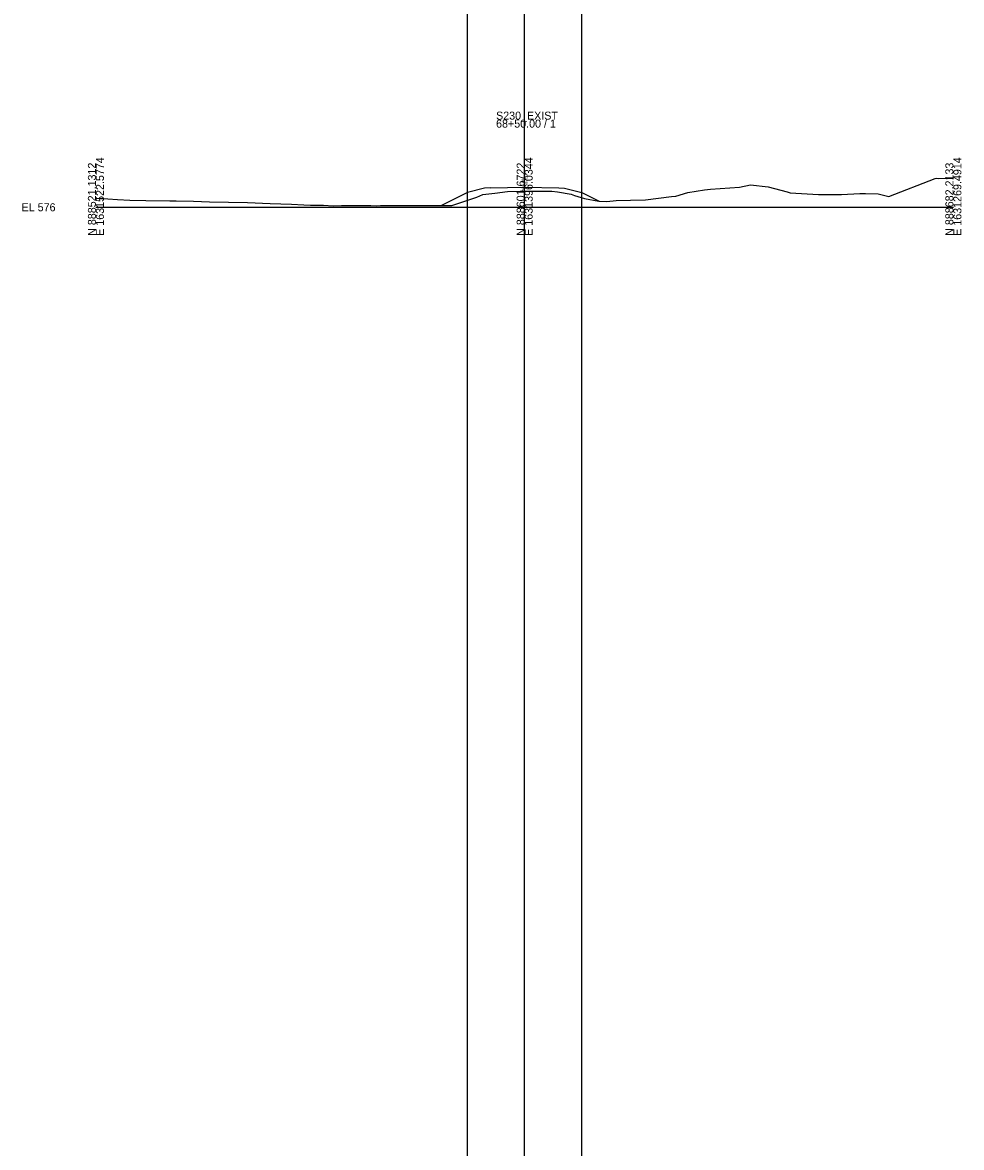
# Model space of a CAD drawing. Extents: x 1631115 to 1631443, y 885974 to 892071.
# Drawn here: x 1631114.8 to 1631443.3, y 887154.7 to 887548.3 of the extents above; entities that cross this region are included whole.
import ezdxf

# ---------------------------------------------------------------- set-up
doc = ezdxf.new("R2010")
doc.units = 0
for name, color, linetype in [('Default', 7, 'Continuous'), ('RD_GPK_XS_Cell', 7, 'Continuous'), ('RD_XS_EarthShd', 7, 'Continuous'), ('RD_XS_ExGround', 7, 'Continuous'), ('RD_XS_Pave', 7, 'Continuous'), ('RD_XS_TieSlope', 7, 'Continuous'), ('RD_XS_TX_Elev_EX', 7, 'Continuous'), ('RD_XS_TX_Elev_PR', 7, 'Continuous')]:
    doc.layers.add(name, color=color, linetype=linetype)

msp = doc.modelspace()

# ---------------------------------------------------------------- linework, layer by layer
at = {"layer": 'Default'}
for p, q in [((1631270.47, 885983.65), (1631270.47, 892068.63)), ((1631290.47, 885983.65), (1631290.47, 892068.63)), ((1631310.47, 885983.65), (1631310.47, 892068.63))]:
    msp.add_line(p, q, dxfattribs=at)
at = {"layer": 'RD_GPK_XS_Cell'}
for p, q in [((1631290.47, 887483.65), (1631290.47, 887514.31)), ((1631140.47, 887483.65), (1631290.47, 887483.65)), ((1631290.47, 887483.65), (1631440.47, 887483.65))]:
    msp.add_line(p, q, dxfattribs=at)
at = {"layer": 'RD_XS_EarthShd'}
for p, q in [((1631278.47, 887490.44), (1631276.47, 887490.28)), ((1631302.47, 887490.44), (1631304.47, 887490.28))]:
    msp.add_line(p, q, dxfattribs=at)
at = {"layer": 'RD_XS_ExGround'}
msp.add_lwpolyline([(1631140.47, 887486.83), (1631141.64, 887486.76), (1631143.05, 887486.67), (1631144.67, 887486.61), (1631147.98, 887486.42), (1631152.3, 887486.11), (1631157.88, 887486.07), (1631166.28, 887485.95), (1631168.52, 887485.86), (1631174.57, 887485.75), (1631180.21, 887485.59), (1631193.5, 887485.29), (1631201.44, 887485.02), (1631208.92, 887484.72), (1631213.18, 887484.52), (1631215.58, 887484.42), (1631219.6, 887484.4), (1631220.09, 887484.39), (1631223.49, 887484.16), (1631226.34, 887484.24), (1631230.36, 887484.21), (1631236.61, 887484.21), (1631238.53, 887484.19), (1631240.03, 887484.21), (1631241.5, 887484.21), (1631249.77, 887484.24), (1631251.42, 887484.21), (1631255.3, 887484.3), (1631262.72, 887484.24), (1631265.05, 887484.23), (1631270.24, 887485.99), (1631273.73, 887487.14), (1631275.88, 887488.13), (1631276.88, 887488.27), (1631280.06, 887488.6), (1631284.47, 887489.19), (1631288.9, 887489.23), (1631290.47, 887489.25), (1631297.3, 887489.32), (1631298.46, 887489.31), (1631299.96, 887489.27), (1631301.98, 887489.04), (1631306.7, 887488.2), (1631307.86, 887487.75), (1631311.39, 887486.73), (1631316.44, 887485.76), (1631319.24, 887485.71), (1631322.45, 887485.96), (1631327.55, 887486.11), (1631332.7, 887486.23), (1631341.84, 887487.43), (1631343.32, 887487.56), (1631347.59, 887488.76), (1631353.43, 887489.77), (1631355.55, 887490), (1631365.69, 887490.68), (1631369.44, 887491.49), (1631375.62, 887490.84), (1631382.27, 887489), (1631383.34, 887488.73), (1631393.28, 887488.11), (1631401.32, 887488.08), (1631407.74, 887488.41), (1631409.67, 887488.43), (1631414.14, 887488.38), (1631417.88, 887487.47), (1631434.11, 887493.76), (1631434.65, 887493.78), (1631435.16, 887493.77), (1631440.47, 887493.87)], dxfattribs=at)
at = {"layer": 'RD_XS_Pave'}
for p, q in [((1631278.47, 887490.44), (1631290.47, 887490.68)), ((1631290.47, 887490.68), (1631302.47, 887490.44))]:
    msp.add_line(p, q, dxfattribs=at)
at = {"layer": 'RD_XS_TieSlope'}
for p, q in [((1631276.47, 887490.28), (1631270.47, 887488.78)), ((1631304.47, 887490.28), (1631310.47, 887488.78)), ((1631270.47, 887488.78), (1631261.41, 887484.25)), ((1631310.47, 887488.78), (1631316.55, 887485.74))]:
    msp.add_line(p, q, dxfattribs=at)

# ---------------------------------------------------------------- texts
at = {"layer": 'RD_GPK_XS_Cell'}
for s, p in [('S230_EXIST', (1631280.47, 887514.31)), ('68+50.00 / 1', (1631280.47, 887511.51)), ('EL 576', (1631114.47, 887482.25))]:
    msp.add_text(s, height=2.8, dxfattribs=at).set_placement(p)
for s, p in [('N 888521.1312', (1631140.47, 887473.65)), ('E 1631522.5774', (1631143.27, 887473.65)), ('N 888601.6722', (1631290.47, 887473.65)), ('E 1631396.0344', (1631293.27, 887473.65)), ('N 888682.2133', (1631440.47, 887473.65)), ('E 1631269.4914', (1631443.27, 887473.65))]:
    msp.add_text(s, height=2.8, rotation=90, dxfattribs=at).set_placement(p)
at = {"layer": 'RD_XS_TX_Elev_EX'}
msp.add_text('581.60', height=1, rotation=90, dxfattribs=at).set_placement((1631290.37, 887489.35))
at = {"layer": 'RD_XS_TX_Elev_PR'}
msp.add_text(' 583.03', height=1, rotation=90, dxfattribs=at).set_placement((1631291.47, 887490.68))

doc.saveas('drawing.dxf')
